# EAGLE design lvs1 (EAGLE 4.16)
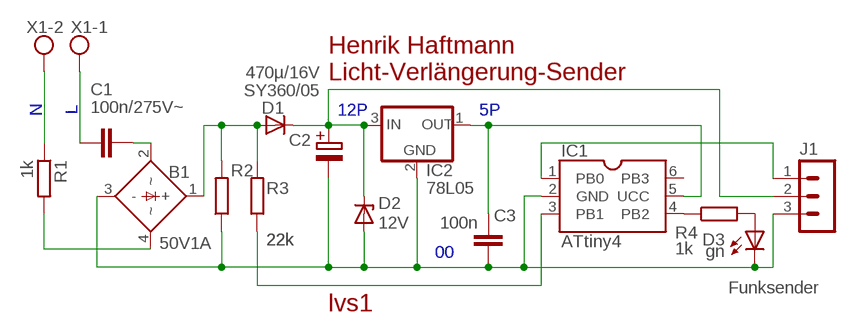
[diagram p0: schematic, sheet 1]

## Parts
B1  50V1A  DBA  [DB1A]
C1  100n/275V~  C15  [C150-084X183]
C2  470µ/16V  E02-10  [E02-10]
C3  100n  C02  [C2]
D1  SY360/05  D01  [R01]
D2  12V  DZ01  [R01]
D3  gn  LED3MM  [LED3MM]
IC1  ATtiny4  TN4SOCKEL  [DIL06]
IC2  78L05  78XX92/  [TO92/]
J1  Funksender  MA03-1  [MA03-1]
R1  1k  R01  [R01]
R2  22k  R01  [R01]
R3  22k  R01  [R01]
R4  1k  R01  [R01]
X1  W237-02P  [W237-132]

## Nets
00: B1.3(-) C2.- C3.2 D2.1(A) D3.K IC1.2(GND) IC2.2(GND) J1.3 R2.1
5P: C3.1 IC1.5(UCC) IC2.1(OUT)
12P: C2.+ D1.2(K) D2.2(K) IC2.3(IN) J1.2
!ZC: IC1.3(PB1) R3.1
L: C1.1 X1.1
N: R1.1 X1.2
N$1: B1.2(~) C1.2
N$2: IC1.1(PB0) J1.1
N$3: B1.1(+) D1.1(A) R2.2 R3.2
N$4: B1.4(~) R1.2
N$5: IC1.4(PB2) R4.1
N$6: D3.A R4.2
Unconnected: IC1.6(PB3)

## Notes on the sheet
- Henrik Haftmann
- Licht-Verlängerung-Sender

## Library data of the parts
B1 = fu:DB: Gleichrichterbrücke 1-phasig
C1 C3 = fu:C: Kondensator
C2 = fu:E: Elektrolytkondensator, gepolt
D1 = fu:D: Diode
D2 = fu:DZ: Z-Diode
D3 = fu:LED: Leuchtdiode
IC1 = fu:TN4: AVR-Mikrocontroller TypFlashRAMADCSignatur ATtiny451232nein0x1E 0x8F 0x0A ATtiny551232ja0x1E 0x8F 0x09 ATtiny9102432nein0x1E 0x90 0x08 ATtiny10102432ja0x1E 0x90 0x03
IC2 = fu:78XX: Spannungsregler positiv (78xx) oder negativ (79xx)
J1 = con-lstb:MA03-1: PIN HEADER
R1-R4 = fu:R: Widerstand
X1 = con-wago-508:W237-02P: WAGO SREW CLAMP

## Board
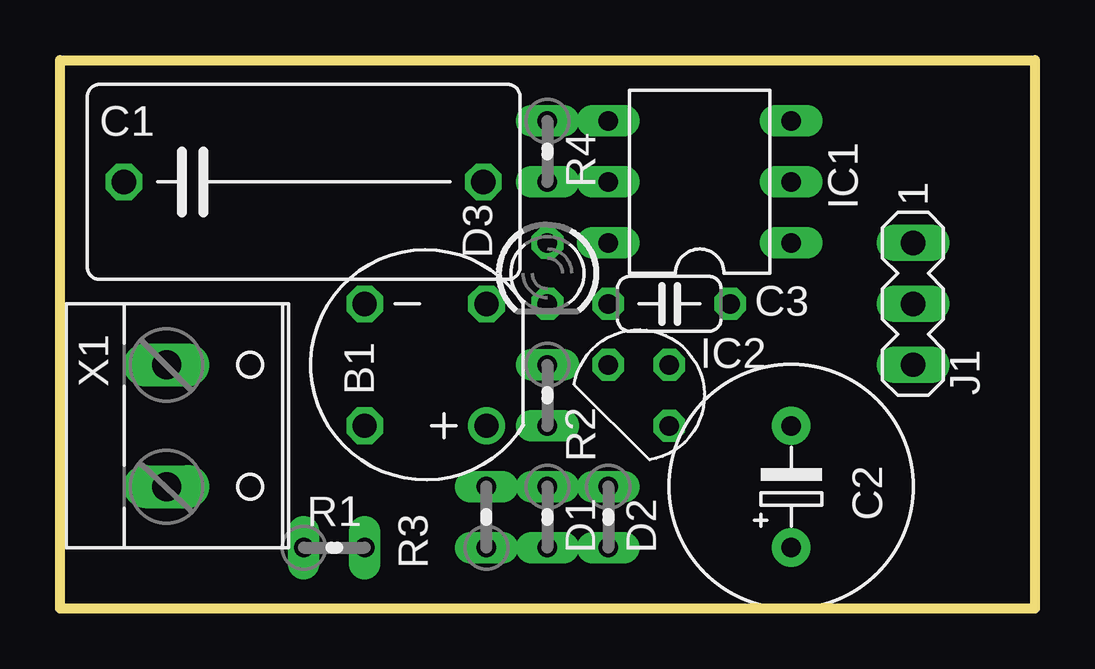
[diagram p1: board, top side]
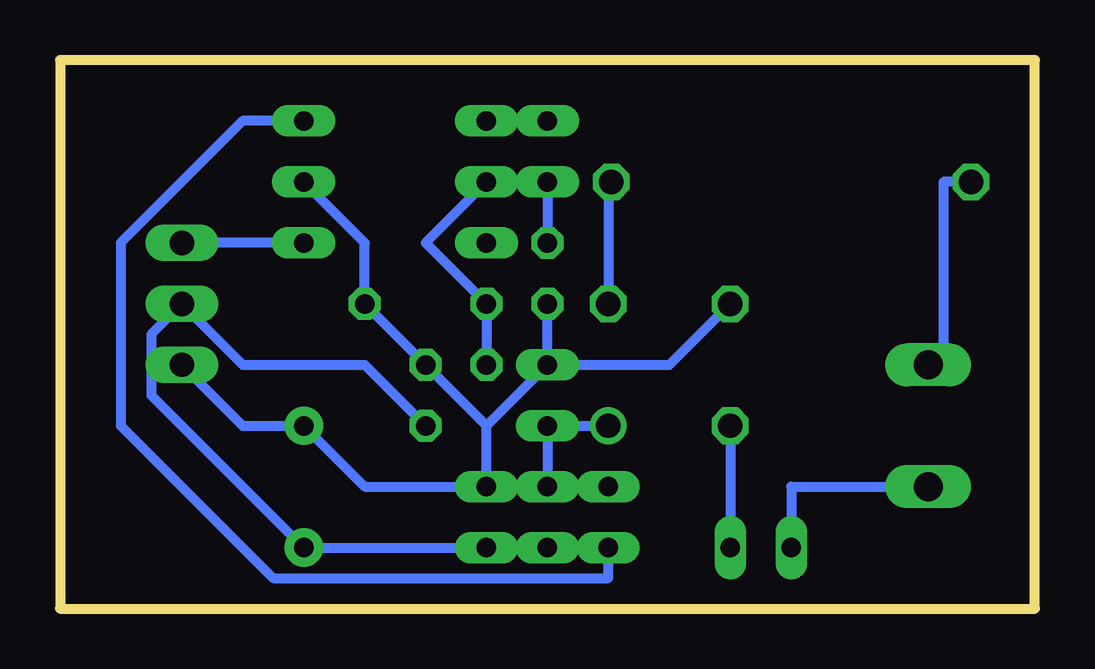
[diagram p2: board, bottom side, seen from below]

Size 40.64 x 22.86 mm. Coordinates in mm from the lower left corner, seen from the top.
Outline: 0,22.86 40.64,22.86 40.64,0 0,0 0,22.86
Copper layers (1*16): Top 0.035mm / dielectric 1.5mm / Bottom 0.035mm
Design rules "default": minimum track width 10mil, minimum drill 0.6mm, track to track 8mil, track to pad 8mil, pad to pad 8mil, via to via 8mil, smd to smd 0mil, copper to edge 0.5mm, drill to drill 8mil, minimum pad ring 10mil, minimum via ring 8mil, stop-mask expansion 4mil, vias tented up to drill 0mil, thermal gap 10mil

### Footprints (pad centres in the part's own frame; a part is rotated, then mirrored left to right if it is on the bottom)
DB1A = drill 1.016 round: 1 -2.54,2.54 | drill 1.016 octagon: 2 -2.54,-2.54; 3 2.54,-2.54; 4 2.54,2.54
C150-084X183 = drill 1.016 octagon: 1 -7.493,0; 2 7.493,0
E02-10 = drill 0.813 pad 1.6 round: + -2.54,0; - 2.54,0
C2 = drill 0.813 octagon: 1 -2.54,0; 2 2.54,0
R01 = drill 0.813 long: 1 -1.27,0; 2 1.27,0
LED3MM = drill 0.813 octagon: A -1.27,0; K 1.27,0
DIL06 = drill 0.813 long: 1 -2.54,-3.81; 2 0,-3.81; 3 2.54,-3.81; 4 2.54,3.81; 5 0,3.81; 6 -2.54,3.81
TO92/ = drill 0.813 octagon: 1 -2.54,0; 2 0,0; 3 0,-2.54
MA03-1 = drill 1.016 long: 1 -2.54,0; 2 0,0; 3 2.54,0
W237-132 = drill 1.194 long: 1 -2.54,-0.635; 2 2.54,-0.635

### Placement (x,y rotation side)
B1  15.24,10.16 180 top
C1  10.16,17.78 0 top
C2  30.48,5.08 90 top
C3  25.4,12.7 0 top
D1  20.32,3.81 270 top
D2  22.86,3.81 270 top
D3  20.32,13.97 270 top
IC1  26.67,17.78 90 top
IC2  25.4,10.16 0 top
J1  35.56,12.7 270 top
R1  11.43,2.54 0 top
R2  20.32,8.89 270 top
R3  17.78,3.81 90 top
R4  2k2  [R01]  20.32,19.05 270 top
X1  5.08,7.62 270 top

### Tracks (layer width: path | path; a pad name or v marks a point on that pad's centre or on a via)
00
  Bottom 0.406: R2.1 15.24,10.16 B1.3 | 22.86,7.62 R2.1 | 22.86,7.62 D2.1 27.94,5.08 C2.- 33.02,7.62 J1.3 | 22.86,7.62 IC2.2 C3.2 27.94,15.24 IC1.2 | R2.1 D3.K
5P
  Bottom 0.406: IC1.5 25.4,15.24 C3.1 IC2.1
12P
  Bottom 0.406: D1.2 D2.2 C2.+ 36.83,8.89 36.83,11.43 J1.2 33.02,10.16 27.94,10.16 IC2.3
!ZC
  Bottom 0.406: R3.1 17.78,1.27 31.75,1.27 38.1,7.62 38.1,15.24 33.02,20.32 IC1.3
L
  Bottom 0.406: X1.1 3.81,10.16 3.81,17.78 C1.1
N
  Bottom 0.406: X1.2 10.16,5.08 R1.1
N$1
  Bottom 0.406: B1.2 17.78,17.78 C1.2
N$2
  Bottom 0.406: IC1.1 J1.1
N$3
  Bottom 0.406: B1.1 R2.2 D1.1 R3.2
N$4
  Bottom 0.406: B1.4 R1.2
N$5
  Bottom 0.406: R4.1 IC1.4
N$6
  Bottom 0.406: R4.2 D3.A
